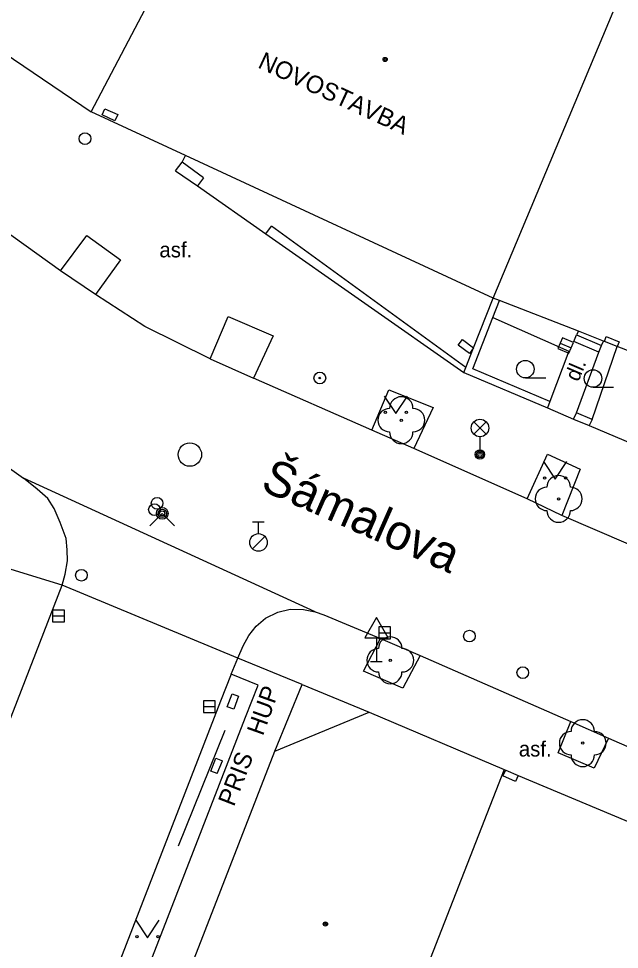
# Model space of a CAD drawing. Extents: x -596229 to -595156, y -1161237 to -1159376.
# Drawn here: x -596199.72 to -596174.06, y -1161042.27 to -1161002.54 of the extents above; entities that cross this region are included whole.
import ezdxf

# ---------------------------------------------------------------- set-up
doc = ezdxf.new("R2010")
doc.units = 0
for name, color, linetype in [('Level 22', 7, 'Continuous'), ('Level 25', 7, 'Continuous'), ('Level 27', 7, 'Continuous'), ('Level 28', 7, 'Continuous'), ('Level 31', 7, 'Continuous'), ('Level 33', 7, 'Continuous'), ('Level 34', 7, 'Continuous'), ('Level 36', 7, 'Continuous'), ('Level 39', 7, 'Continuous'), ('Nazvy ulic', 7, 'Continuous'), ('plynovod - povrch.  znaky - PRIS skut. velikost', 7, 'Continuous'), ('silnoproud - povrch.  znaky a  RIS  skut. velikost', 7, 'Continuous'), ('Specificka linie pasportu komunikaci', 7, 'Continuous'), ('TM - budovy zdene_ betonove - VN', 7, 'Continuous'), ('TM - budovy zdene_ betonove - VP', 7, 'Continuous'), ('TM - chodniky - VP', 7, 'Continuous'), ('TM - komunikace - VP', 7, 'Continuous'), ('TM - plot drateny_ kovovy - VP', 7, 'Continuous'), ('TM - plot dreveny - VP', 7, 'Continuous'), ('TM - plot zivy neuzavreny', 7, 'Continuous'), ('TM - podezdivka plotu - VP', 7, 'Continuous'), ('TM - popis objektu', 7, 'Continuous'), ('TM - popis povrchu', 7, 'Continuous'), ('TM - rozhrani ploch obecne - VP', 7, 'Continuous'), ('TM - schody - VP', 7, 'Continuous'), ('TM - vjezd na pozemek', 7, 'Continuous')]:
    doc.layers.add(name, color=color, linetype=linetype)

msp = doc.modelspace()

# ---------------------------------------------------------------- linework, layer by layer
at = {"layer": 'Level 22'}
for centre in [(-596183.38, -1161019.68), (-596176.66, -1161023.04), (-596183.85, -1161029.93), (-596175.63, -1161033.47)]:
    msp.add_circle(centre, 0.05, dxfattribs=at)
for centre, start, end in [((-596183.38, -1161019.18), 0, 180), ((-596183.88, -1161019.68), 90, 270), ((-596182.88, -1161019.68), 270, 90), ((-596183.38, -1161020.18), 180, 0), ((-596176.66, -1161022.54), 0, 180), ((-596177.16, -1161023.04), 90, 270), ((-596176.16, -1161023.04), 270, 90), ((-596176.66, -1161023.54), 180, 0), ((-596183.85, -1161029.43), 0, 180), ((-596184.35, -1161029.93), 90, 270), ((-596183.35, -1161029.93), 270, 90), ((-596183.85, -1161030.43), 180, 0), ((-596175.63, -1161032.97), 0, 180), ((-596176.13, -1161033.47), 90, 270), ((-596175.13, -1161033.47), 270, 90), ((-596175.63, -1161033.97), 180, 0)]:
    msp.add_arc(centre, 0.5, start, end, dxfattribs=at)
at = {"layer": 'Level 25'}
for radius in [0.25, 0.0303]:
    msp.add_circle((-596186.86, -1161017.88), radius, dxfattribs=at)
at = {"layer": 'Level 27'}
for p, q in [((-596176.59, -1161016.392), (-596176.13, -1161016.588)), ((-596198.27, -1161028.04), (-596197.77, -1161028.04)), ((-596184.34, -1161028.76), (-596183.84, -1161028.76)), ((-596191.83, -1161031.91), (-596191.33, -1161031.91))]:
    msp.add_line(p, q, dxfattribs=at)
for points in [[(-596176.688, -1161016.622), (-596176.228, -1161016.818), (-596176.032, -1161016.358), (-596176.492, -1161016.162)], [(-596198.27, -1161028.29), (-596197.77, -1161028.29), (-596197.77, -1161027.79), (-596198.27, -1161027.79)], [(-596184.34, -1161029.01), (-596183.84, -1161029.01), (-596183.84, -1161028.51), (-596184.34, -1161028.51)], [(-596191.83, -1161032.16), (-596191.33, -1161032.16), (-596191.33, -1161031.66), (-596191.83, -1161031.66)]]:
    msp.add_lwpolyline(points, close=True, dxfattribs=at)
msp.add_circle((-596192.41, -1161021.15), 0.5, dxfattribs=at)
at = {"layer": 'Level 28'}
for p, q in [((-596189.73, -1161024.025), (-596189.23, -1161024.025)), ((-596189.48, -1161024.525), (-596189.48, -1161024.025)), ((-596189.738, -1161025.172), (-596189.208, -1161024.642))]:
    msp.add_line(p, q, dxfattribs=at)
for centre, radius in [((-596193.81, -1161023.23), 0.25), ((-596193.92, -1161023.5), 0.25), ((-596189.48, -1161024.9), 0.375), ((-596197.04, -1161026.3), 0.25), ((-596180.47, -1161028.9), 0.25), ((-596178.19, -1161030.46), 0.25)]:
    msp.add_circle(centre, radius, dxfattribs=at)
at = {"layer": 'Level 31'}
msp.add_lwpolyline([(-596194.12, -1161024.19), (-596193.59, -1161023.66), (-596193.06, -1161024.19)], dxfattribs=at)
for centre, radius in [((-596196.89, -1161007.66), 0.25), ((-596193.59, -1161023.66), 0.25), ((-596193.59, -1161023.66), 0.18), ((-596193.59, -1161023.66), 0.11)]:
    msp.add_circle(centre, radius, dxfattribs=at)
at = {"layer": 'Level 33'}
for p, q in [((-596180.285, -1161020.28), (-596179.755, -1161019.75)), ((-596180.285, -1161019.75), (-596179.755, -1161020.28)), ((-596180.02, -1161020.39), (-596180.02, -1161021.14))]:
    msp.add_line(p, q, dxfattribs=at)
for centre, radius in [((-596180.02, -1161020.015), 0.375), ((-596180.02, -1161021.14), 0.2), ((-596180.02, -1161021.14), 0.145), ((-596180.02, -1161021.14), 0.0876)]:
    msp.add_circle(centre, radius, dxfattribs=at)
at = {"layer": 'Level 34'}
for p, q in [((-596184.44, -1161028.972), (-596184.44, -1161029.99)), ((-596184.69, -1161029.99), (-596184.19, -1161029.99))]:
    msp.add_line(p, q, dxfattribs=at)
msp.add_lwpolyline([(-596184.94, -1161028.972), (-596183.94, -1161028.972), (-596184.44, -1161028.106)], close=True, dxfattribs=at)
at = {"layer": 'Level 36'}
for p, q in [((-596178.08, -1161017.875), (-596177.205, -1161017.875)), ((-596175.19, -1161018.275), (-596174.315, -1161018.275))]:
    msp.add_line(p, q, dxfattribs=at)
for points in [[(-596184.11, -1161018.65), (-596183.61, -1161019.4), (-596183.11, -1161018.65)], [(-596177.31, -1161021.45), (-596176.81, -1161022.2), (-596176.31, -1161021.45)], [(-596194.72, -1161041.03), (-596194.22, -1161041.78), (-596193.72, -1161041.03)]]:
    msp.add_lwpolyline(points, dxfattribs=at)
for centre, radius in [((-596178.08, -1161017.5), 0.375), ((-596175.19, -1161017.9), 0.375), ((-596184.06, -1161019.35), 0.05), ((-596183.161, -1161019.35), 0.05), ((-596177.26, -1161022.15), 0.05), ((-596176.361, -1161022.15), 0.05), ((-596194.67, -1161041.73), 0.05), ((-596193.771, -1161041.73), 0.05)]:
    msp.add_circle(centre, radius, dxfattribs=at)
at = {"layer": 'Level 39'}
for centre, radius in [((-596184.07, -1161004.28), 0.09), ((-596184.07, -1161004.28), 0.0398), ((-596186.62, -1161041.19), 0.09), ((-596186.62, -1161041.19), 0.0398)]:
    msp.add_circle(centre, radius, dxfattribs=at)
at = {"layer": 'plynovod - povrch.  znaky - PRIS skut. velikost'}
for points in [[(-596196.16, -1161006.65), (-596196.04, -1161006.38), (-596195.49, -1161006.63), (-596195.62, -1161006.9)], [(-596195.62, -1161006.9), (-596196.16, -1161006.65)], [(-596190.81, -1161031.92), (-596190.61, -1161031.36), (-596190.33, -1161031.46), (-596190.53, -1161032.02), (-596190.81, -1161031.92)]]:
    msp.add_lwpolyline(points, dxfattribs=at)
at = {"layer": 'silnoproud - povrch.  znaky a  RIS  skut. velikost'}
for points in [[(-596180.47, -1161016.83), (-596180.95, -1161016.48), (-596180.77, -1161016.23), (-596180.29, -1161016.59)], [(-596174.7, -1161016.32), (-596174.63, -1161016.11), (-596174.08, -1161016.34), (-596174.16, -1161016.53)], [(-596180.29, -1161016.59), (-596180.47, -1161016.83)], [(-596191.24, -1161034.77), (-596191.52, -1161034.66), (-596191.3, -1161034.11), (-596191.02, -1161034.22)], [(-596191.24, -1161034.77), (-596191.02, -1161034.22)], [(-596179.05, -1161034.87), (-596178.92, -1161034.63)], [(-596178.39, -1161034.85), (-596178.5, -1161035.1), (-596179.05, -1161034.87)]]:
    msp.add_lwpolyline(points, dxfattribs=at)
at = {"layer": 'Specificka linie pasportu komunikaci'}
for points in [[(-596187.06, -1161027.86), (-596199.51, -1161022.16)], [(-596190.36, -1161029.84), (-596197.87, -1161026.73)], [(-596187.61, -1161030.97), (-596190.36, -1161029.84)]]:
    msp.add_lwpolyline(points, dxfattribs=at)
at = {"layer": 'TM - budovy zdene_ betonove - VN'}
for points in [[(-596188.78, -1161033.81), (-596187.61, -1161030.97)], [(-596187.61, -1161030.97), (-596184.75, -1161032.15)]]:
    msp.add_lwpolyline(points, dxfattribs=at)
at = {"layer": 'TM - budovy zdene_ betonove - VP'}
for points in [[(-596196.62, -1161006.52), (-596191.85, -1160997.43)], [(-596179.45, -1161014.47), (-596174.33, -1161002.24)], [(-596201.59, -1161003.15), (-596196.62, -1161006.52)], [(-596192.59, -1161008.38), (-596196.62, -1161006.52)], [(-596179.45, -1161014.47), (-596192.59, -1161008.38)], [(-596179.19, -1161014.57), (-596179.45, -1161014.47)], [(-596175.81, -1161015.88), (-596179.19, -1161014.57)], [(-596174.75, -1161016.3), (-596175.81, -1161015.88)], [(-596174.7, -1161016.32), (-596174.75, -1161016.3)], [(-596174.16, -1161016.53), (-596174.7, -1161016.32)], [(-596171.29, -1161017.65), (-596174.16, -1161016.53)], [(-596188.78, -1161033.81), (-596184.75, -1161032.15)], [(-596184.75, -1161032.15), (-596178.98, -1161034.6)], [(-596194.07, -1161047.4), (-596188.78, -1161033.81)], [(-596178.98, -1161034.6), (-596183.85, -1161047.05)], [(-596178.98, -1161034.6), (-596178.92, -1161034.63)], [(-596178.92, -1161034.63), (-596178.39, -1161034.85)], [(-596178.39, -1161034.85), (-596169.1, -1161038.74)]]:
    msp.add_lwpolyline(points, dxfattribs=at)
at = {"layer": 'TM - chodniky - VP'}
for points in [[(-596197.94, -1161013.31), (-596196.81, -1161011.8), (-596195.37, -1161012.84), (-596196.44, -1161014.32)], [(-596191.54, -1161017.06), (-596190.77, -1161015.26), (-596188.85, -1161016.08), (-596189.69, -1161017.89)], [(-596184.64, -1161020.1), (-596183.91, -1161018.39), (-596182.02, -1161019.14), (-596182.84, -1161020.89)], [(-596178, -1161023.04), (-596177.13, -1161021.13), (-596175.74, -1161021.77), (-596176.53, -1161023.75)], [(-596197.87, -1161026.73), (-596200.04, -1161026.05)], [(-596182.57, -1161029.73), (-596183.31, -1161031.12), (-596185, -1161030.39), (-596184.27, -1161029)], [(-596198.27, -1161053.6), (-596190.03, -1161032.36), (-596189.5, -1161030.99), (-596190.65, -1161030.52)], [(-596174.53, -1161033.25), (-596175.14, -1161034.54), (-596176.68, -1161033.88), (-596176.14, -1161032.54)]]:
    msp.add_lwpolyline(points, dxfattribs=at)
at = {"layer": 'TM - komunikace - VP'}
for points in [[(-596197.94, -1161013.31), (-596202.45, -1161010.07)], [(-596214.48, -1161011.47), (-596199.51, -1161022.16)], [(-596196.44, -1161014.32), (-596197.94, -1161013.31)], [(-596191.54, -1161017.06), (-596194.34, -1161015.68), (-596196.44, -1161014.32)], [(-596191.54, -1161017.06), (-596189.69, -1161017.89)], [(-596184.64, -1161020.1), (-596189.69, -1161017.89)], [(-596182.84, -1161020.89), (-596184.64, -1161020.1)], [(-596178, -1161023.04), (-596182.84, -1161020.89)], [(-596197.87, -1161026.73), (-596197.74, -1161026.25), (-596197.63, -1161025.68), (-596197.65, -1161025.21), (-596197.7, -1161024.73), (-596197.95, -1161024.05), (-596198.2, -1161023.45), (-596198.48, -1161023.02), (-596198.93, -1161022.62), (-596199.51, -1161022.16)], [(-596176.53, -1161023.75), (-596178, -1161023.04)], [(-596170.73, -1161026.24), (-596176.53, -1161023.75)], [(-596205.88, -1161047.38), (-596197.87, -1161026.73)], [(-596190.14, -1161029.31), (-596189.89, -1161028.88), (-596189.58, -1161028.48), (-596189.18, -1161028.13), (-596188.66, -1161027.88), (-596188.13, -1161027.75), (-596187.56, -1161027.77), (-596187.06, -1161027.86)], [(-596187.06, -1161027.86), (-596186.69, -1161027.99)], [(-596186.69, -1161027.99), (-596184.27, -1161029)], [(-596184.27, -1161029), (-596182.57, -1161029.73)], [(-596190.36, -1161029.84), (-596190.14, -1161029.31)], [(-596190.65, -1161030.52), (-596190.36, -1161029.84)], [(-596182.57, -1161029.73), (-596176.14, -1161032.54)], [(-596190.65, -1161030.52), (-596191.101, -1161031.684), (-596199.43, -1161053.16)], [(-596176.14, -1161032.54), (-596174.53, -1161033.25)], [(-596174.53, -1161033.25), (-596169.8, -1161035.32)]]:
    msp.add_lwpolyline(points, dxfattribs=at)
at = {"layer": 'TM - plot drateny_ kovovy - VP'}
for points in [[(-596192.09, -1161009.68), (-596189.16, -1161011.72)], [(-596179.47, -1161015.3), (-596179.19, -1161014.57)], [(-596180.32, -1161017.49), (-596179.47, -1161015.3)], [(-596177.04, -1161018.88), (-596180.32, -1161017.49)], [(-596175.23, -1161019.65), (-596175.89, -1161019.36)]]:
    msp.add_lwpolyline(points, dxfattribs=at)
at = {"layer": 'TM - plot dreveny - VP'}
for points in [[(-596192.74, -1161008.66), (-596192.59, -1161008.38)], [(-596191.83, -1161009.33), (-596192.74, -1161008.66)], [(-596180.62, -1161017.43), (-596188.92, -1161011.39)]]:
    msp.add_lwpolyline(points, dxfattribs=at)
at = {"layer": 'TM - plot zivy neuzavreny'}
msp.add_lwpolyline([(-596192.89, -1161037.85), (-596190.9, -1161032.91)], dxfattribs=at)
at = {"layer": 'TM - podezdivka plotu - VP'}
for points in [[(-596193.02, -1161009.03), (-596192.74, -1161008.66)], [(-596193.02, -1161009.03), (-596192.09, -1161009.68)], [(-596191.83, -1161009.33), (-596192.09, -1161009.68)], [(-596189.16, -1161011.72), (-596188.92, -1161011.39)], [(-596189.16, -1161011.72), (-596180.71, -1161017.65)], [(-596180.29, -1161016.59), (-596179.45, -1161014.47)], [(-596180.62, -1161017.43), (-596180.29, -1161016.59)], [(-596180.71, -1161017.65), (-596180.62, -1161017.43)], [(-596180.71, -1161017.65), (-596177.14, -1161019.15)], [(-596177.04, -1161018.88), (-596177.14, -1161019.15)], [(-596176.02, -1161019.63), (-596175.89, -1161019.36)], [(-596176.02, -1161019.63), (-596175.36, -1161019.91)], [(-596175.23, -1161019.65), (-596175.36, -1161019.91)]]:
    msp.add_lwpolyline(points, dxfattribs=at)
at = {"layer": 'TM - rozhrani ploch obecne - VP'}
for points in [[(-596179.47, -1161015.3), (-596176.22, -1161016.73), (-596177.04, -1161018.88)], [(-596175.81, -1161015.88), (-596175.89, -1161016.04)], [(-596174.95, -1161016.77), (-596176.01, -1161016.32), (-596175.89, -1161016.04)], [(-596174.83, -1161016.49), (-596174.75, -1161016.3)], [(-596175.89, -1161019.36), (-596174.95, -1161016.77)], [(-596175.23, -1161019.65), (-596174.16, -1161016.53)], [(-596174.95, -1161016.77), (-596174.83, -1161016.49)]]:
    msp.add_lwpolyline(points, dxfattribs=at)
at = {"layer": 'TM - schody - VP'}
msp.add_lwpolyline([(-596175.89, -1161016.04), (-596174.83, -1161016.49)], dxfattribs=at)
at = {"layer": 'TM - vjezd na pozemek'}
for points in [[(-596177.14, -1161019.15), (-596176.02, -1161019.63)], [(-596175.36, -1161019.91), (-596172.77, -1161021)]]:
    msp.add_lwpolyline(points, dxfattribs=at)

# ---------------------------------------------------------------- texts
at = {"layer": 'Nazvy ulic'}
msp.add_text('Šámalova', height=1.5, rotation=336.1809, dxfattribs=at).set_placement((-596189.449, -1161022.634))
at = {"layer": 'TM - popis objektu'}
for s, rotation, p in [('NOVOSTAVBA', 335.1678, (-596189.55, -1161004.61)), ('HUP', 70.27, (-596189.29, -1161033.19)), ('PRIS', 68.79, (-596190.53, -1161036.21))]:
    msp.add_text(s, height=0.75, rotation=rotation, dxfattribs=at).set_placement(p)
at = {"layer": 'TM - popis povrchu'}
for p in [(-596193.71, -1161012.73), (-596178.36, -1161034.04)]:
    msp.add_text('asf.', height=0.65, dxfattribs=at).set_placement(p)
msp.add_text('dl.', height=0.65, rotation=66.9218, dxfattribs=at).set_placement((-596175.82, -1161018.07))

doc.saveas('drawing.dxf')
